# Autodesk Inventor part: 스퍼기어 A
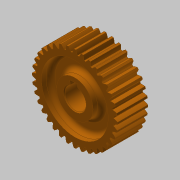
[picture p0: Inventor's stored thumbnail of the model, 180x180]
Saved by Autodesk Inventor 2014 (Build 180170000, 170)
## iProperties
Created: 2020-04
Part Number: 스퍼기어 A
Material: Steel
Document SubType Name: Modeling
Designer: mduedu
Categories: <?xml version="1.0" encoding="UTF-16"?> <MemberInstance><Categories><FamilyTemplate><FamilyTemplateParameter ValueType="xs:double" Id="1" ObjectReferenceKey="da
Density: 7.85 g/cm^3
Mass: 238.004 g
Surface Area: 130.635 cm^2
Volume: 30.319 cm^3
Appearance: 주황색
CustomPartVersion: 1
Author: mduedu
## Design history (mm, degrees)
sketch "Sketch1"
  geometry: C1 r 28.2 at (0, 0)
  constraints: 1 centre point
  dimensions: "d0" = 56.4 diameter of C1 (= da_da)
extrude "Extrusion1" new body sketch "Sketch1" distance "d1" = 20 (= da_b); taper "d2" = 0 deg
workplane "Work Plane2"
sketch "Sketch2"
  geometry: C1 r 28.2 at (0, 0) reference; C2 r 27 at (0, 0)
  constraints: 1 centre point, 1 coincident
  dimensions: "d3" = 54 diameter of C2 (= da_dw)
feature "피치 지름" sketch "Sketch2" dims "d4" = 10, "d5" = 0
workplane "Work Plane8"
workplane "Work Plane9"
feature "스퍼 기어" dims "da_b" = 20, "da_d" = 54, "da_aw" = 45, "da_da" = 56.4, "da_df" = 51.129, "da_dw" = 54, angle "da_beta" = 0 deg, "da_lefttooth" = 0, "da_righttooth" = 0
node "작업 평면11"
sketch "스케치3"
  geometry: C1 r 12 at (0, 0); C2 r 22 at (0, 0); 1 further point
  constraints: 2 centre point, 2 coincident
  dimensions: "d49" = 24 diameter of C1; "d50" = 44 diameter of C2
extrude "돌출2" cut sketch "스케치3" distance "d51" = 6; taper "d52" = 0 deg
fillet "모깎기1" dims "d53" = 3
sketch "스케치4" dims "d17" = 0
  geometry: L1 (-3.06, 6.296)-(1.921, 6.731); L2 (1.921, 6.731)-(1.68, 9.483); L3 (1.68, 9.483)-(-3.301, 9.047); L4 (-3.301, 9.047)-(-3.06, 6.296); L5 (-3.728, 42.608)-(3.728, -42.608) reference; A1 r 7 centre (0, 0) between (-3.06, 6.296) and (1.921, 6.731); 1 further point
  constraints: 8 end point, 4 perpendicular, 2 point on circle, 1 centre point, 1 coincident
  dimensions: "d54" = 14 diameter of A1; "d63" = 16.3 dimension on A1 L3; "d64" = 5 distance of L2.end L3.end
extrude "돌출3" cut sketch "스케치4" stored distance "d58" = 6; taper "d59" = 0 deg
chamfer "모따기1" distance "d60" = 0.5; stored, may be unused: second distance "d61" = 2, angle "d62" = 45 deg
body "Solid1"
mirror "대칭1"
body "Srf1"
other parameters: "d16" = 45 (= da_aw), "d34" = 5 deg (computed from da_z), "d39" = 0, "d41" = 0, "d43" = 45 (= da_aw), "d46" = 45 (= da_aw), "d47" = 0, "d48" = 0
